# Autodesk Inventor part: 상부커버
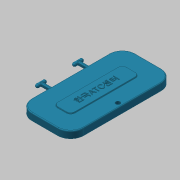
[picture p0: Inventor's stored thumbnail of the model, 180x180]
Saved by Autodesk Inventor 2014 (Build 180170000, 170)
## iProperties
Created: 2016-02
Part Number: 상부커버
Material: ABS 플라스틱
Document SubType Name: Modeling
Designer: mduedu
Density: 1.06 g/cm^3
Mass: 61.4476 g
Surface Area: 174.433 cm^2
Volume: 57.9694 cm^3
Appearance: 터키옥색
Author: mduedu
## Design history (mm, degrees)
sketch "스케치1"
  geometry: L1 (30, 60)-(-30, 60); L2 (-30, 60)-(-30, -60); L3 (-30, -60)-(30, -60); L4 (30, -60)-(30, 60); L5 (30, 60)-(-30, -60); L6 (-30, 60)-(30, -60); 1 further point
  constraints: 12 end point, 2 midpoint, 2 parallel, 1 horizontal, 1 perpendicular
  dimensions: "d0" = 60 distance of L2.end L3.end; "d2" = 120 distance of L1.end L2.end
extrude "돌출1" new body sketch "스케치1" distance "d3" = 8; taper "d4" = 0 deg
fillet "모깎기1" dims "d5" = 15
node "작업 평면1"
sketch "스케치7"
  geometry: L1 (-39, 4)-(129, 4) reference; L2 (65, 2)-(68, 2); L3 (68, 2)-(68, 6); L4 (68, 6)-(65, 6); L5 (65, 6)-(65, 2); L6 (65, 2)-(68, 6); L7 (68, 2)-(65, 6); 2 further points
  constraints: 12 end point, 2 midpoint, 2 parallel, 1 horizontal, 1 perpendicular, 1 point on line
  dimensions: "d33" = 4 distance of L2.end L3.end; "d35" = 3 distance of L3.end L4.end; "d36" = 20 distance from line of L5 point (45, 0)
extrude "돌출3" join sketch "스케치7" distance "d37" = 15; taper "d38" = 0 deg
fillet "모깎기6" dims "d39" = 2
node "작업 평면3"
sketch "스케치8"
  geometry: A1 r 2 centre (-13, 2) between (-13, 4) and (-13, 0) reference; 2 further points
  constraints: 1 coincident, 1 vertical alignment, 2 other
extrude "돌출4" join sketch "스케치8" stored distance "d40" = 12; taper "d41" = 0 deg
fillet "모깎기7" dims "d42" = 2
fillet "모깎기8" dims "d43" = 1
fillet "모깎기9" dims "d44" = 1
sketch "스케치2"
  geometry: L1 (30, 45)-(30, -45) reference; L2 (15, -60)-(-15, -60) reference; L3 (-30, -45)-(-30, 45) reference; L4 (-15, 60)-(15, 60) reference; L5 (25, 45)-(25, -45); L6 (15, -55)-(-15, -55); L7 (-25, -45)-(-25, 45); L8 (-15, 55)-(15, 55); A1 r 15 centre (15, 45) between (30, 45) and (15, 60) reference; A2 r 15 centre (15, -45) between (15, -60) and (30, -45) reference; A3 r 15 centre (-15, -45) between (-30, -45) and (-15, -60) reference; A4 r 15 centre (-15, 45) between (-15, 60) and (-30, 45) reference; A5 r 10 centre (15, 45) between (25, 45) and (15, 55); A6 r 10 centre (15, -45) between (15, -55) and (25, -45); A7 r 10 centre (-15, -45) between (-25, -45) and (-15, -55); A8 r 10 centre (-15, 45) between (-15, 55) and (-25, 45); 4 further points
  constraints: 8 end point, 8 point on circle, 4 centre point, 4 midpoint, 7 other
  dimensions: "d8" = 5 distance between parallel lines of L7 L3
hole "구멍1" sketch "스케치2" at (25, 0) diameter "d9" = 5; stored, may be unused: countersink angle "d13" = 90 deg, drill point angle "d15" = 118 deg; dims "d10" = 6, "d11" = 4, "d12" = 2, "d14" = 8
sketch "스케치3"
  geometry: L1 (10, -40)-(-10, -40); L2 (-10, -40)-(-10, 40); L3 (-10, 40)-(10, 40); L4 (10, 40)-(10, -40); L5 (10, -40)-(-10, 40); L6 (-10, -40)-(10, 40); 1 further point
  constraints: 12 end point, 2 midpoint, 2 parallel, 1 horizontal, 1 perpendicular
  dimensions: "d16" = 80 distance of L1.end L2.end; "d18" = 20 distance of L2.end L3.end
extrude "돌출2" join sketch "스케치3" distance "d19" = 1; taper "d20" = 0 deg
fillet "모깎기2" dims "d21" = 5
fillet "모깎기3" dims "d22" = 0.3
sketch "스케치4"
  geometry: 2 further points
  constraints: 1 coincident, 1 other
feature "엠보싱1" sketch "스케치4" dims "d8" = 5, "d24" = 0.5, "d25" = 0
fillet "모깎기10" dims "d45" = 1
node "솔리드1"
mirror "대칭1"
node "절단 모서리 투영1"
